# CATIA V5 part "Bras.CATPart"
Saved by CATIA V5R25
Part number: Part9
Bounding box of the stored display mesh (mm): x -145 to 148.432, y -12.5 to 12.5, z -1.029 to 12.862
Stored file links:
  C:\Users\m000605\Desktop\Projet FAB liseuse\Bras.CATPart
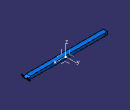
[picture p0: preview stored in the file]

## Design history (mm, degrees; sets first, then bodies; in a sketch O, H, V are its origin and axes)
AxisSystem1: origin (0, 0, 0), X (1, 0, 0), Y (0, 1, 0), Z (0, 0, 1)
Set1
  Sketch1 on XY plane of AxisSystem1, origin (0, 0, 0), H (1, 0, 0), V (0, 1, 0)
    line L1 (-145, 7.5) -> (145, 7.5)
    line L2 (145, 7.5) -> (145, -7.5)
    line L3 (145, -7.5) -> (-145, -7.5)
    line L4 (-145, -7.5) -> (-145, 7.5)
    length L1 = 290
    length L2 = 15
    horizontal: L1 H, L3 H
    vertical: L2 V, L4 V
    symmetry: L3 L1 H, L2 L4 V
Body1 (main body)
  Pad1: profile Sketch1, direction (0, 0, 1), length 10
  Sketch2 on face of Pad1 from Sketch1.L1, origin (0, 7.5, 0), H (-1, 0, 0), V (0, 0, 1)
    circle A1 centre (137.45, 5) radius 2.55
    point P1 (137.45, 5)
    reference projected line E1 (145, 0) -> (145, 10) from edge [face of Pad1 from Sketch1.L4 | face of Pad1 from Sketch1.L1]
    reference projected line E2 (-145, 0) -> (145, 0) from edge [start face of Pad1 | face of Pad1 from Sketch1.L1]
    radius A1 = 2.55
    distance A1 E1 = 5
    distance P1 E2 = 5
  Pocket1: profile Sketch2, direction (0, -1, 0), through (limit type 6)
  Sketch3 on ZX plane of AxisSystem1, origin (0, 0, 0), H (0, 0, 1), V (1, 0, 0)
    point P1 (0, 145)
    line L1 (0, 145) -> (10, 145)
    point P2 (10, 145)
    reference projected point E1 (10, 145) from vertex [face of Pad1 from Sketch1.L1 | end face of Pad1 | face of Pad1 from Sketch1.L2]
    line L2 (10, 145) -> (0, 139)
    point P3 (0, 139)
    line L3 (0, 139) -> (0, 145)
    length L1 = 10
    length L3 = 6
    coincidence: P1 V, P2 E1, P3 V
    vertical: L3 V
  Pocket2: profile Sketch3, direction (0, -1, 0), through (limit type 6), offset 6, opposite side length 8
  Sketch4 on face of Pocket2 from Sketch3.L2, origin (102.2059, 0, -61.3235), H (0, 1, 0), V (0.5145, 0, 0.8575)
    line L1 (12.5, 86.5149) -> (12.5, 71.5149)
    line L2 (12.5, 71.5149) -> (-12.5, 71.5149)
    line L3 (-12.5, 71.5149) -> (-12.5, 86.5149)
    reference projected line E1 (-7.5, 71.5149) -> (7.5, 71.5149) from edge [start face of Pad1 | face of Pocket2 from Sketch3.L2]
    line L4 (-12.5, 86.5149) -> (-7.5, 86.5149)
    point P5 (-7.5, 86.5149)
    line L5 (12.5, 86.5149) -> (7.5, 86.5149)
    line L6 (7.5, 86.5149) -> (7.5, 83.1768)
    line L7 (7.5, 83.1768) -> (-7.5, 83.1768)
    line L8 (-7.5, 83.1768) -> (-7.5, 86.5149)
    point P9 (-7.5, 86.5149)
    reference projected line E2 (7.5, 83.1768) -> (7.5, 71.5149) from edge [face of Pocket2 from Sketch3.L2 | face of Pad1 from Sketch1.L1]
    reference projected line E3 (-7.5, 83.1768) -> (-7.5, 71.5149) from edge [face of Pad1 from Sketch1.L3 | face of Pocket2 from Sketch3.L2]
    reference projected line E4 (-7.5, 83.1768) -> (7.5, 83.1768) from edge [face of Pocket2 from Sketch3.L2 | end face of Pad1]
    length L5 = 5
    length L3 = 15
    horizontal: L2 H, L4 H, L5 H, L7 H
    vertical: L1 V, L3 V, L6 V
    symmetry: L1 L3 V
    coincidence: L2 E1, L8 P5, E2 L6, E3 L8, L7 E4, P9 P5, L5 L4
  Pad2: profile Sketch4, direction (0.8575, 0, -0.5145), length 2
  Sketch5 on end face of Pad2, origin (103.9209, 0, -62.3525), H (0, 1, 0), V (0.5145, 0, 0.8575)
    line L1 (-7.5, 83.1768) -> (7.5, 83.1768)
    line L2 (7.5, 83.1768) -> (7.5, 78.1768)
    line L3 (7.5, 78.1768) -> (-7.5, 78.1768)
    line L4 (-7.5, 78.1768) -> (-7.5, 83.1768)
    reference projected line E1 (7.5, 86.5149) -> (7.5, 83.1768) from edge [face of Pad2 from Sketch4.L6 | end face of Pad2]
    reference projected line E2 (-7.5, 83.1768) -> (-7.5, 86.5149) from edge [face of Pad2 from Sketch4.L8 | end face of Pad2]
    reference projected line E3 (7.5, 83.1768) -> (-7.5, 83.1768) from edge [face of Pad2 from Sketch4.L7 | end face of Pad2]
    length L2 = 5
    horizontal: L1 H, L3 H
    vertical: L2 V, L4 V
    coincidence: L2 E1, L4 E2, E3 L1
  Pocket3: profile Sketch5, direction (-0.8575, 0, 0.5145), through (limit type 6)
